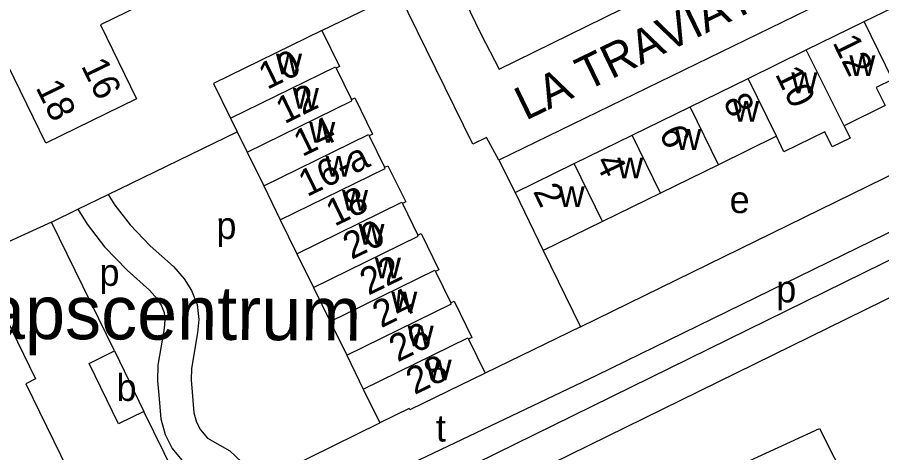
# Model space of a CAD drawing. Extents: x 159441 to 162086, y 388175 to 389787.
# Drawn here: x 161032.2 to 161160.6, y 388817 to 388881.7 of the extents above; entities that cross this region are included whole.
import ezdxf

# ---------------------------------------------------------------- set-up
doc = ezdxf.new("R2010")
doc.units = 0
for name, color, linetype in [('BLT_Basislijn', 7, 'Continuous'), ('BLT_Bebouwing', 7, 'Continuous'), ('BLT_Bebouwing_beschrifting', 7, 'Continuous'), ('BLT_Centroide', 7, 'Continuous'), ('BLT_Huisnummer', 7, 'Continuous'), ('BLT_Huisnummer_ tussenligend', 7, 'Continuous'), ('BLT_Huisnummer_reeks', 7, 'Continuous'), ('BLT_Onderverdeling_panden', 7, 'Continuous'), ('BLT_Straatnaam', 7, 'Continuous')]:
    doc.layers.add(name, color=color, linetype=linetype)

msp = doc.modelspace()

# ---------------------------------------------------------------- linework, layer by layer
at = {"layer": 'BLT_Basislijn'}
for p, q in [((161077.43, 388879.73), (161088.87, 388885.25)), ((161216.74, 388872.6), (161082.14, 388806.54)), ((161218.94, 388868.11), (161025.1, 388772.97)), ((161045.71, 388855.38), (161064.87, 388864.69)), ((161103.74, 388860.46), (161101.91, 388863.83)), ((161041.19, 388853.18), (161045.71, 388855.38)), ((161037.27, 388851.28), (161041.19, 388853.18)), ((161037.27, 388851.28), (161024.55, 388845.47))]:
    msp.add_line(p, q, dxfattribs=at)
for points in [[(161087.68, 388906.85), (161101.06, 388879.2), (161103.8, 388873.99), (161127.2, 388885.49)], [(161160.47, 388897.55), (161164.2, 388889.91), (161103.74, 388860.46)], [(161101.91, 388863.83), (161099.9, 388862.83), (161088.87, 388885.25)], [(161079.32, 388809.98), (161118.3, 388828.54), (161215.09, 388875.8)], [(161115.87, 388835.74), (161187.08, 388870.54)], [(161103.74, 388860.46), (161106.15, 388855.68)], [(161045.71, 388855.38), (161046.68, 388853.81), (161048.97, 388850.86), (161051.97, 388847.76), (161055.4, 388844.7), (161057, 388842.87), (161058.11, 388841.11), (161058.93, 388839.05), (161059.17, 388836.83), (161059, 388834.84), (161058.08, 388829.55), (161058.04, 388827.87), (161058.2, 388826.02), (161058.46, 388822.98), (161058.85, 388821.58), (161059.44, 388820.45), (161060.45, 388819.21), (161062.32, 388818.15), (161063.79, 388817.3), (161065.58, 388815.65), (161065.98, 388814.83), (161069.54, 388813.54)], [(161041.19, 388853.18), (161042.57, 388850.96), (161045.19, 388847.58), (161048.51, 388844.16), (161051.84, 388841.18), (161052.98, 388839.87), (161053.64, 388838.83), (161054.03, 388837.83), (161054.15, 388836.78), (161054.03, 388835.49), (161053.09, 388830.04), (161053.03, 388827.72), (161053.22, 388825.58), (161053.52, 388822.09), (161054.17, 388819.75), (161055.23, 388817.69), (161057.16, 388815.33), (161059.84, 388813.8), (161060.82, 388813.25), (161061.49, 388812.62), (161062.37, 388810.82), (161063.59, 388810.38)], [(161046.65, 388832.14), (161037.27, 388851.28)], [(161110.35, 388847.07), (161115.87, 388835.74)], [(161115.87, 388835.74), (161101.71, 388828.87)], [(161058.54, 388807.89), (161051.02, 388823.15)], [(161072.21, 388814.64), (161086.06, 388821.47)], [(161126.83, 388809.34), (161151.36, 388820.64), (161177.47, 388769.07)]]:
    msp.add_lwpolyline(points, dxfattribs=at)
at = {"layer": 'BLT_Bebouwing'}
for p, q in [((161079.56, 388874.12), (161081.84, 388869.47)), ((161063.9, 388866.68), (161064.87, 388864.69)), ((161064.87, 388864.69), (161066.36, 388861.65)), ((161084.49, 388864.07), (161086.76, 388859.41)), ((161066.36, 388861.65), (161068.82, 388856.64)), ((161068.82, 388856.64), (161071.28, 388851.61)), ((161106.15, 388855.68), (161110.35, 388847.07)), ((161089.41, 388854.02), (161091.7, 388849.35)), ((161071.28, 388851.61), (161073.75, 388846.58)), ((161073.75, 388846.58), (161076.21, 388841.55)), ((161094.33, 388843.94), (161096.62, 388839.3)), ((161076.21, 388841.55), (161078.67, 388836.53)), ((161078.67, 388836.53), (161081.14, 388831.5)), ((161099.26, 388833.9), (161101.71, 388828.87)), ((161046.65, 388832.14), (161051.02, 388823.15)), ((161081.14, 388831.5), (161083.6, 388826.48)), ((161083.6, 388826.48), (161086.06, 388821.47))]:
    msp.add_line(p, q, dxfattribs=at)
for points in [[(161049.92, 388869.55), (161036.47, 388862.97), (161029.88, 388876.5), (161028.88, 388876.02), (161024.9, 388884.14), (161028.71, 388886.03), (161012.27, 388919.6), (160967.97, 388897.83)], [(161069.16, 388898.26), (161071.4, 388893.68), (161044.56, 388880.55), (161049.92, 388869.55)], [(161158.02, 388881.04), (161166.63, 388885.26)], [(161149.39, 388876.83), (161158.02, 388881.04)], [(161077.43, 388879.73), (161061.35, 388871.87), (161063.9, 388866.68)], [(161077.43, 388879.73), (161080.05, 388874.36), (161079.56, 388874.12)], [(161140.77, 388872.61), (161149.39, 388876.83)], [(161132.15, 388868.4), (161140.77, 388872.61)], [(161162.23, 388872.44), (161159.8, 388871.26), (161161.12, 388868.57), (161155.02, 388865.58)], [(161081.84, 388869.47), (161082.34, 388869.71), (161084.98, 388864.32), (161084.49, 388864.07)], [(161123.53, 388864.18), (161132.15, 388868.4)], [(161155.02, 388865.58), (161155.93, 388863.74), (161153.27, 388862.44), (161152.18, 388864.68), (161146.1, 388861.71), (161144.98, 388864.01)], [(161114.91, 388859.96), (161123.53, 388864.18)], [(161144.98, 388864.01), (161136.36, 388859.79)], [(161106.15, 388855.68), (161114.91, 388859.96)], [(161136.36, 388859.79), (161127.74, 388855.58)], [(161086.76, 388859.41), (161087.27, 388859.65), (161089.91, 388854.27), (161089.41, 388854.02)], [(161127.74, 388855.58), (161119.12, 388851.36)], [(161119.12, 388851.36), (161110.35, 388847.07)], [(161091.7, 388849.35), (161092.2, 388849.59), (161094.83, 388844.19), (161094.33, 388843.94)], [(161024.55, 388845.47), (161025.4, 388843.76), (161026.83, 388844.47), (161034.9, 388827.99), (161033.46, 388827.27), (161040.64, 388812.57)], [(161096.62, 388839.3), (161097.11, 388839.53), (161099.75, 388834.14), (161099.26, 388833.9)], [(161051.02, 388823.15), (161047.25, 388821.32), (161042.88, 388830.3), (161046.65, 388832.14)], [(161101.71, 388828.87), (161090.53, 388823.42), (161090.43, 388823.61), (161086.06, 388821.47)]]:
    msp.add_lwpolyline(points, dxfattribs=at)
at = {"layer": 'BLT_Onderverdeling_panden'}
for p, q in [((161162.23, 388872.44), (161158.02, 388881.04)), ((161155.02, 388865.58), (161149.39, 388876.83)), ((161144.98, 388864.01), (161140.77, 388872.61)), ((161136.36, 388859.79), (161132.15, 388868.4)), ((161127.74, 388855.58), (161123.53, 388864.18)), ((161119.12, 388851.36), (161114.91, 388859.96))]:
    msp.add_line(p, q, dxfattribs=at)
for points in [[(161063.9, 388866.68), (161079.47, 388874.31), (161079.56, 388874.12)], [(161066.36, 388861.65), (161081.93, 388869.28), (161081.84, 388869.47)], [(161068.82, 388856.64), (161084.39, 388864.27), (161084.49, 388864.07)], [(161071.28, 388851.61), (161086.84, 388859.24), (161086.76, 388859.41)], [(161073.75, 388846.58), (161089.31, 388854.21), (161089.41, 388854.02)], [(161076.21, 388841.55), (161091.78, 388849.18), (161091.7, 388849.35)], [(161078.67, 388836.53), (161094.23, 388844.15), (161094.33, 388843.94)], [(161081.14, 388831.5), (161096.7, 388839.13), (161096.62, 388839.3)], [(161083.6, 388826.48), (161099.15, 388834.1), (161099.26, 388833.9)]]:
    msp.add_lwpolyline(points, dxfattribs=at)

# ---------------------------------------------------------------- texts
at = {"layer": 'BLT_Bebouwing_beschrifting'}
msp.add_text('Gemeenschapscentrum', height=8, rotation=359.7264, dxfattribs=at).set_placement((160969.72, 388834.23))
at = {"layer": 'BLT_Centroide'}
for s, p in [('w', (161070.64, 388873.19)), ('w', (161155.81, 388872.97)), ('w', (161147.19, 388870.41)), ('w', (161073.14, 388868.09)), ('w', (161138.56, 388866.19)), ('w', (161075.57, 388863.06)), ('w', (161129.95, 388862)), ('w', (161078.01, 388858.03)), ('w', (161121.33, 388857.78)), ('w', (161080.45, 388852.97)), ('w', (161112.63, 388853.5)), ('e', (161138.03, 388852.61)), ('p', (161061.79, 388848.77)), ('w', (161082.89, 388847.94)), ('w', (161085.33, 388842.91)), ('p', (161044.42, 388841.81)), ('p', (161144.95, 388839.36)), ('w', (161087.77, 388837.88)), ('w', (161090.2, 388832.81)), ('w', (161092.87, 388827.78)), ('b', (161046.95, 388824.73)), ('t', (161094.4, 388818.69))]:
    msp.add_text(s, height=4, dxfattribs=at).set_placement(p)
at = {"layer": 'BLT_Huisnummer'}
for s, rotation, p in [('10', 26.0631, (161069.33, 388870.88)), ('10', 296.0638, (161144.72, 388873.26)), ('14', 26.0631, (161074.53, 388860.9)), ('6', 296.0638, (161127.46, 388864.51)), ('18', 26.0631, (161079.33, 388850.56)), ('2', 296.0638, (161108.77, 388855.84)), ('24', 26.0631, (161086.25, 388835.5)), ('28', 26.0631, (161091.23, 388825.58))]:
    msp.add_text(s, height=4, rotation=rotation, dxfattribs=at).set_placement(p)
at = {"layer": 'BLT_Huisnummer_ tussenligend'}
for s, rotation, p in [('12', 296.0638, (161153.26, 388877.95)), ('12', 26.0631, (161071.89, 388865.78)), ('8', 296.0638, (161136.99, 388869.2)), ('4', 296.0638, (161117.96, 388860.24)), ('20', 26.0631, (161081.85, 388845.64)), ('22', 26.0631, (161084.37, 388840.34)), ('26', 26.0631, (161088.71, 388830.43))]:
    msp.add_text(s, height=4, rotation=rotation, dxfattribs=at).set_placement(p)
at = {"layer": 'BLT_Huisnummer_reeks'}
for s, rotation, p in [('16', 295.9624, (161041.63, 388874.48)), ('18', 296.0616, (161034.89, 388871.26)), ('16-a', 26.0631, (161075.25, 388854.96))]:
    msp.add_text(s, height=4, rotation=rotation, dxfattribs=at).set_placement(p)
at = {"layer": 'BLT_Straatnaam'}
msp.add_text('LA TRAVIATA', height=5, rotation=25.8394, dxfattribs=at).set_placement((161107.72, 388866.29))

doc.saveas('drawing.dxf')
